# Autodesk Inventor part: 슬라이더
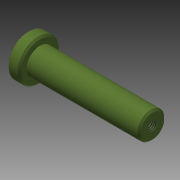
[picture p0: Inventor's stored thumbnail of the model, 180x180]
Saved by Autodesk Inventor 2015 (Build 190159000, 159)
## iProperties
Created: 2011-04
Part Number: 슬라이더
Document SubType Name: Modeling
Density: 1 g/cm^3
Material: 일반
Appearance: 올리브 녹색
Author: pww
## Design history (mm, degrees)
sketch "스케치1"
  geometry: L1 (-7, 0)-(63, 0); L2 (63, 0)-(63, 7.5); L3 (63, 7.5)-(0, 7.5); L4 (-7, 0)-(-7, 11.5); L5 (-7, 11.5)-(0, 11.5); L6 (0, 11.5)-(0, 7.5); 1 further point
  constraints: 12 end point, 3 perpendicular, 2 horizontal, 2 point on line, 1 parallel
  dimensions: "d1" = 70 distance of L1.start L1.end; "d19" = 15 diameter of L3 L1; "d20" = 7 distance of L4.end L5.end; "d21" = 23 diameter of L5 L1
revolve "회전1" stored, may be unused: angle "d4" = 90 deg
chamfer "모따기1" distance "d16" = 1; stored, may be unused: second distance "d17" = 2, angle "d18" = 45 deg
hole "구멍2" diameter "d24" = 4.917; stored, may be unused: countersink angle "d28" = 90 deg, drill point angle "d30" = 118 deg; dims "d22" = 10, "d23" = 10, "d25" = 10, "d26" = 4, "d27" = 2, "d29" = 13
node "솔리드1"
